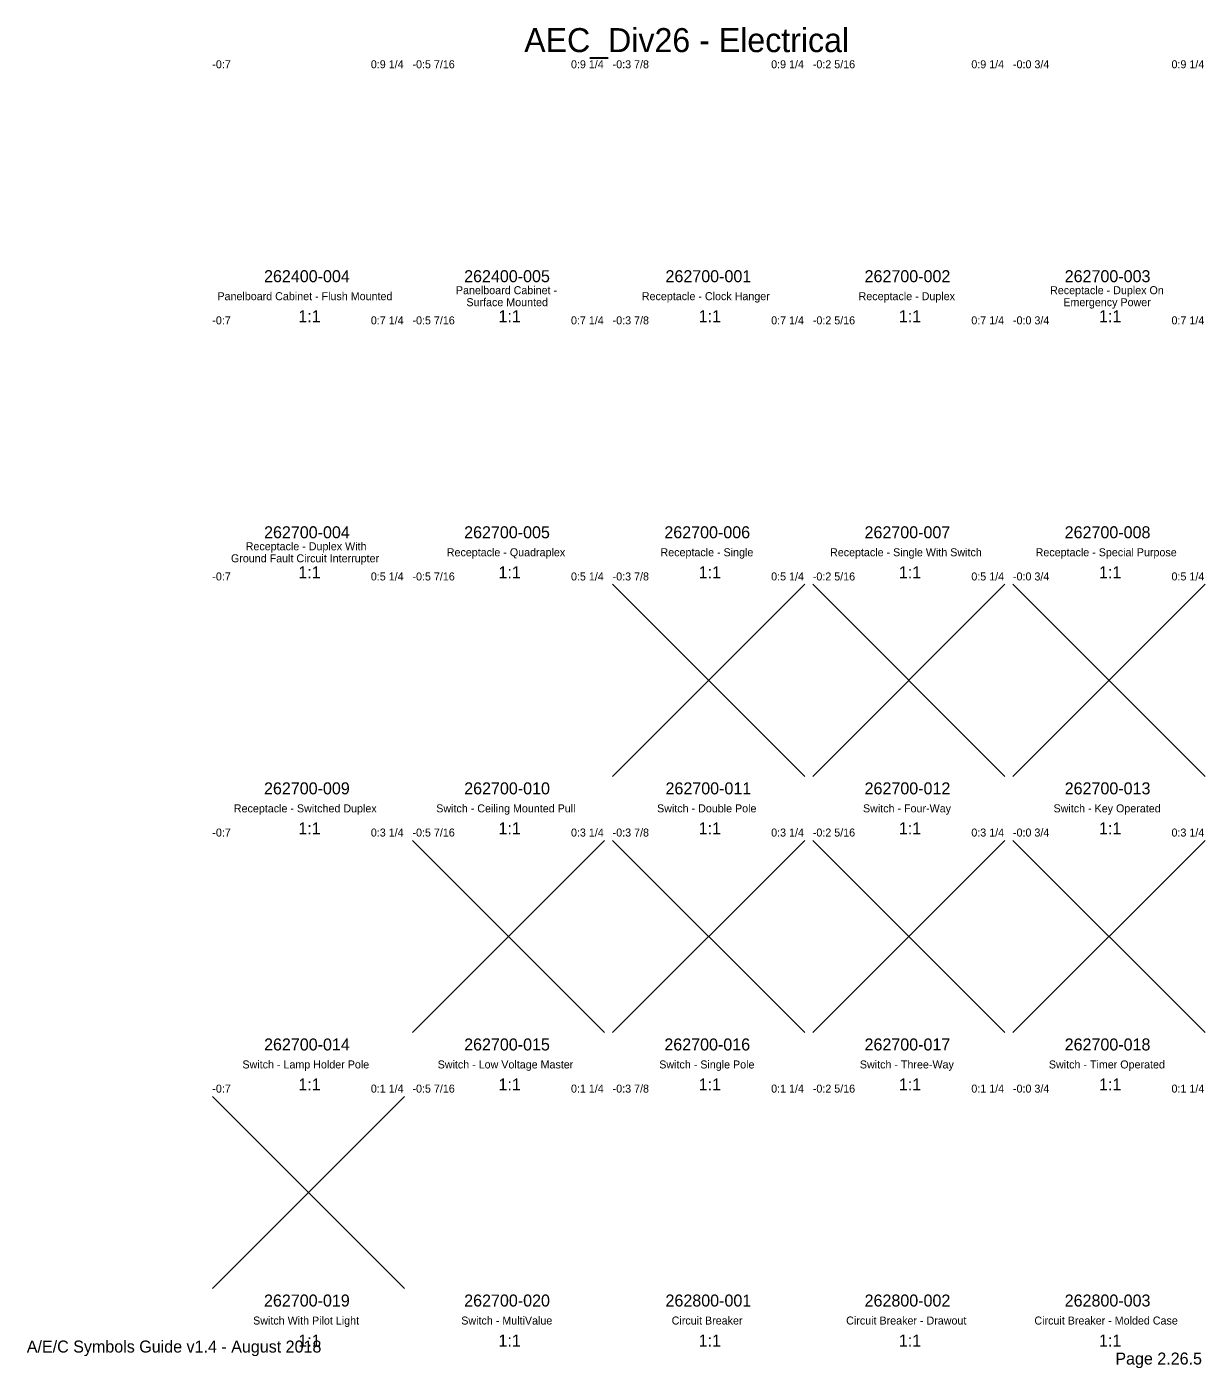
# Model space of a CAD drawing. Extents: x -0.8 to 0, y 0 to 31.6.
# Drawn here: x -0.766 to 0, y -0.01 to 0.863 of the extents above; entities that cross this region are included whole.
import ezdxf

# ---------------------------------------------------------------- set-up
doc = ezdxf.new("R2010")
doc.units = 0
for name, color, linetype in [('Cell1', 7, 'Continuous'), ('Cell10', 7, 'Continuous'), ('Cell11', 7, 'Continuous'), ('Cell12', 7, 'Continuous'), ('Cell13', 7, 'Continuous'), ('Cell14', 7, 'Continuous'), ('Cell15', 7, 'Continuous'), ('Cell16', 7, 'Continuous'), ('Cell17', 7, 'Continuous'), ('Cell18', 7, 'Continuous'), ('Cell19', 7, 'Continuous'), ('Cell2', 7, 'Continuous'), ('Cell20', 7, 'Continuous'), ('Cell21', 7, 'Continuous'), ('Cell22', 7, 'Continuous'), ('Cell23', 7, 'Continuous'), ('Cell24', 7, 'Continuous'), ('Cell25', 7, 'Continuous'), ('Cell3', 7, 'Continuous'), ('Cell4', 7, 'Continuous'), ('Cell5', 7, 'Continuous'), ('Cell6', 7, 'Continuous'), ('Cell7', 7, 'Continuous'), ('Cell8', 7, 'Continuous'), ('Cell9', 7, 'Continuous'), ('Default', 7, 'Continuous'), ('G-ANNO-REDL', 7, 'Continuous'), ('G-ANNO-TEXT', 7, 'Continuous'), ('OriginText', 7, 'Continuous')]:
    doc.layers.add(name, color=color, linetype=linetype)

msp = doc.modelspace()

# ---------------------------------------------------------------- linework, layer by layer
at = {"layer": 'G-ANNO-REDL'}
for p, q in [((-0.38542, 0.5), (-0.26042, 0.375)), ((-0.38542, 0.375), (-0.26042, 0.5)), ((-0.25521, 0.5), (-0.13021, 0.375)), ((-0.25521, 0.375), (-0.13021, 0.5)), ((-0.125, 0.5), (0, 0.375)), ((-0.125, 0.375), (0, 0.5)), ((-0.51563, 0.33333), (-0.39063, 0.20833)), ((-0.51563, 0.20833), (-0.39063, 0.33333)), ((-0.38542, 0.33333), (-0.26042, 0.20833)), ((-0.38542, 0.20833), (-0.26042, 0.33333)), ((-0.25521, 0.33333), (-0.13021, 0.20833)), ((-0.25521, 0.20833), (-0.13021, 0.33333)), ((-0.125, 0.33333), (0, 0.20833)), ((-0.125, 0.20833), (0, 0.33333)), ((-0.64583, 0.16667), (-0.52083, 0.04167)), ((-0.64583, 0.04167), (-0.52083, 0.16667))]:
    msp.add_line(p, q, dxfattribs=at)

# ---------------------------------------------------------------- texts
at = {"layer": 'Cell1'}
for s, height, p in [('262400-004', 0.007813, (-0.61219, 0.69662)), ('Panelboard Cabinet - Flush Mounted', 0.0052083, (-0.64252, 0.6849)), ('1:1', 0.007813, (-0.58991, 0.67057))]:
    msp.add_text(s, height=height, dxfattribs=at).set_placement(p)
at = {"layer": 'Cell10'}
for s, height, p in [('262700-008', 0.007813, (-0.09138, 0.52995)), ('Receptacle - Special Purpose', 0.0052083, (-0.11027, 0.51823)), ('1:1', 0.007813, (-0.06908, 0.50391))]:
    msp.add_text(s, height=height, dxfattribs=at).set_placement(p)
at = {"layer": 'Cell11'}
for s, height, p in [('262700-009', 0.007813, (-0.61221, 0.36328)), ('Receptacle - Switched Duplex', 0.0052083, (-0.63183, 0.35156)), ('1:1', 0.007813, (-0.58991, 0.33724))]:
    msp.add_text(s, height=height, dxfattribs=at).set_placement(p)
at = {"layer": 'Cell12'}
for s, height, p in [('262700-010', 0.007813, (-0.48199, 0.36328)), ('Switch - Ceiling Mounted Pull', 0.0052083, (-0.50018, 0.35156)), ('1:1', 0.007813, (-0.45971, 0.33724))]:
    msp.add_text(s, height=height, dxfattribs=at).set_placement(p)
at = {"layer": 'Cell13'}
for s, height, p in [('262700-011', 0.007813, (-0.35104, 0.36328)), ('Switch - Double Pole', 0.0052083, (-0.35653, 0.35156)), ('1:1', 0.007813, (-0.3295, 0.33724))]:
    msp.add_text(s, height=height, dxfattribs=at).set_placement(p)
at = {"layer": 'Cell14'}
for s, height, p in [('262700-012', 0.007813, (-0.22154, 0.36328)), ('Switch - Four-Way', 0.0052083, (-0.22259, 0.35156)), ('1:1', 0.007813, (-0.19929, 0.33724))]:
    msp.add_text(s, height=height, dxfattribs=at).set_placement(p)
at = {"layer": 'Cell15'}
for s, height, p in [('262700-013', 0.007813, (-0.09137, 0.36328)), ('Switch - Key Operated', 0.0052083, (-0.09863, 0.35156)), ('1:1', 0.007813, (-0.06908, 0.33724))]:
    msp.add_text(s, height=height, dxfattribs=at).set_placement(p)
at = {"layer": 'Cell16'}
for s, height, p in [('262700-014', 0.007813, (-0.61219, 0.19661)), ('Switch - Lamp Holder Pole', 0.0052083, (-0.62625, 0.1849)), ('1:1', 0.007813, (-0.58991, 0.17057))]:
    msp.add_text(s, height=height, dxfattribs=at).set_placement(p)
at = {"layer": 'Cell17'}
for s, height, p in [('262700-015', 0.007813, (-0.48203, 0.19661)), ('Switch - Low Voltage Master', 0.0052083, (-0.49927, 0.1849)), ('1:1', 0.007813, (-0.45971, 0.17057))]:
    msp.add_text(s, height=height, dxfattribs=at).set_placement(p)
at = {"layer": 'Cell18'}
for s, height, p in [('262700-016', 0.007813, (-0.35179, 0.19661)), ('Switch - Single Pole', 0.0052083, (-0.35512, 0.18489)), ('1:1', 0.007813, (-0.3295, 0.17057))]:
    msp.add_text(s, height=height, dxfattribs=at).set_placement(p)
at = {"layer": 'Cell19'}
for s, height, p in [('262700-017', 0.007813, (-0.22158, 0.19661)), ('Switch - Three-Way', 0.0052083, (-0.22461, 0.1849)), ('1:1', 0.007813, (-0.19929, 0.17057))]:
    msp.add_text(s, height=height, dxfattribs=at).set_placement(p)
at = {"layer": 'Cell2'}
for s, height, p in [('262400-005', 0.007813, (-0.48203, 0.69662)), ('Panelboard Cabinet - ', 0.0052083, (-0.48739, 0.6888)), ('Surface Mounted', 0.0052083, (-0.48056, 0.68099)), ('1:1', 0.007813, (-0.45971, 0.67057))]:
    msp.add_text(s, height=height, dxfattribs=at).set_placement(p)
at = {"layer": 'Cell20'}
for s, height, p in [('262700-018', 0.007813, (-0.09138, 0.19661)), ('Switch - Timer Operated', 0.0052083, (-0.10166, 0.1849)), ('1:1', 0.007813, (-0.06908, 0.17057))]:
    msp.add_text(s, height=height, dxfattribs=at).set_placement(p)
at = {"layer": 'Cell21'}
for s, height, p in [('262700-019', 0.007813, (-0.61221, 0.02995)), ('Switch With Pilot Light', 0.0052083, (-0.61929, 0.01823)), ('1:1', 0.007813, (-0.58991, 0.00391))]:
    msp.add_text(s, height=height, dxfattribs=at).set_placement(p)
at = {"layer": 'Cell22'}
for s, height, p in [('262700-020', 0.007813, (-0.48199, 0.02995)), ('Switch - MultiValue', 0.0052083, (-0.48391, 0.01823)), ('1:1', 0.007813, (-0.45971, 0.00391))]:
    msp.add_text(s, height=height, dxfattribs=at).set_placement(p)
at = {"layer": 'Cell23'}
for s, height, p in [('262800-001', 0.007813, (-0.35104, 0.02995)), ('Circuit Breaker', 0.0052083, (-0.34702, 0.01823)), ('1:1', 0.007813, (-0.3295, 0.0039))]:
    msp.add_text(s, height=height, dxfattribs=at).set_placement(p)
at = {"layer": 'Cell24'}
for s, height, p in [('262800-002', 0.007813, (-0.22154, 0.02995)), ('Circuit Breaker - Drawout', 0.0052083, (-0.23351, 0.01823)), ('1:1', 0.007813, (-0.19929, 0.00391))]:
    msp.add_text(s, height=height, dxfattribs=at).set_placement(p)
at = {"layer": 'Cell25'}
for s, height, p in [('262800-003', 0.007813, (-0.09137, 0.02995)), ('Circuit Breaker - Molded Case', 0.0052083, (-0.11107, 0.01823)), ('1:1', 0.007813, (-0.06908, 0.00391))]:
    msp.add_text(s, height=height, dxfattribs=at).set_placement(p)
at = {"layer": 'Cell3'}
for s, height, p in [('262700-001', 0.007813, (-0.35104, 0.69661)), ('Receptacle - Clock Hanger', 0.0052083, (-0.36644, 0.6849)), ('1:1', 0.007813, (-0.3295, 0.67057))]:
    msp.add_text(s, height=height, dxfattribs=at).set_placement(p)
at = {"layer": 'Cell4'}
for s, height, p in [('262700-002', 0.007813, (-0.22154, 0.69662)), ('Receptacle - Duplex', 0.0052083, (-0.22544, 0.6849)), ('1:1', 0.007813, (-0.19929, 0.67057))]:
    msp.add_text(s, height=height, dxfattribs=at).set_placement(p)
at = {"layer": 'Cell5'}
for s, height, p in [('262700-003', 0.007813, (-0.09137, 0.69662)), ('Receptacle - Duplex On ', 0.0052083, (-0.10087, 0.6888)), ('Emergency Power', 0.0052083, (-0.09227, 0.68099)), ('1:1', 0.007813, (-0.06908, 0.67057))]:
    msp.add_text(s, height=height, dxfattribs=at).set_placement(p)
at = {"layer": 'Cell6'}
for s, height, p in [('262700-004', 0.007813, (-0.61219, 0.52995)), ('Receptacle - Duplex With ', 0.0052083, (-0.62413, 0.52214)), ('Ground Fault Circuit Interrupter', 0.0052083, (-0.63372, 0.51432)), ('1:1', 0.007813, (-0.58991, 0.50391))]:
    msp.add_text(s, height=height, dxfattribs=at).set_placement(p)
at = {"layer": 'Cell7'}
for s, height, p in [('262700-005', 0.007813, (-0.48203, 0.52995)), ('Receptacle - Quadraplex', 0.0052083, (-0.49333, 0.51823)), ('1:1', 0.007813, (-0.45971, 0.50391))]:
    msp.add_text(s, height=height, dxfattribs=at).set_placement(p)
at = {"layer": 'Cell8'}
for s, height, p in [('262700-006', 0.007813, (-0.35179, 0.52995)), ('Receptacle - Single', 0.0052083, (-0.35431, 0.51823)), ('1:1', 0.007813, (-0.3295, 0.50391))]:
    msp.add_text(s, height=height, dxfattribs=at).set_placement(p)
at = {"layer": 'Cell9'}
for s, height, p in [('262700-007', 0.007813, (-0.22158, 0.52995)), ('Receptacle - Single With Switch', 0.0052083, (-0.24402, 0.51823)), ('1:1', 0.007813, (-0.19929, 0.50391))]:
    msp.add_text(s, height=height, dxfattribs=at).set_placement(p)
at = {"layer": 'Default'}
msp.add_text('AEC_Div26 - Electrical', height=0.015625, dxfattribs=at).set_placement((-0.44295, 0.84635))
at = {"layer": 'G-ANNO-TEXT'}
for s, p in [('A/E/C Symbols Guide v1.4 - August 2018', (-0.76652, 0)), ('Page 2.26.5', (-0.05842, -0.00781))]:
    msp.add_text(s, height=0.0078125, dxfattribs=at).set_placement(p)
at = {"layer": 'OriginText'}
for s, p in [('-0:7', (-0.64583, 0.83583)), ('0:9 1/4', (-0.54272, 0.83583)), ('-0:5 7/16', (-0.51563, 0.83583)), ('0:9 1/4', (-0.41252, 0.83583)), ('-0:3 7/8', (-0.38542, 0.83583)), ('0:9 1/4', (-0.28231, 0.83583)), ('-0:2 5/16', (-0.25521, 0.83583)), ('0:9 1/4', (-0.1521, 0.83583)), ('-0:0 3/4', (-0.125, 0.83583)), ('0:9 1/4', (-0.02189, 0.83583)), ('-0:7', (-0.64583, 0.66917)), ('0:7 1/4', (-0.54272, 0.66917)), ('-0:5 7/16', (-0.51563, 0.66917)), ('0:7 1/4', (-0.41252, 0.66917)), ('-0:3 7/8', (-0.38542, 0.66917)), ('0:7 1/4', (-0.28231, 0.66917)), ('-0:2 5/16', (-0.25521, 0.66917)), ('0:7 1/4', (-0.1521, 0.66917)), ('-0:0 3/4', (-0.125, 0.66917)), ('0:7 1/4', (-0.02189, 0.66917)), ('-0:7', (-0.64583, 0.5025)), ('0:5 1/4', (-0.54272, 0.5025)), ('-0:5 7/16', (-0.51563, 0.5025)), ('0:5 1/4', (-0.41252, 0.5025)), ('-0:3 7/8', (-0.38542, 0.5025)), ('0:5 1/4', (-0.28231, 0.5025)), ('-0:2 5/16', (-0.25521, 0.5025)), ('0:5 1/4', (-0.1521, 0.5025)), ('-0:0 3/4', (-0.125, 0.5025)), ('0:5 1/4', (-0.02189, 0.5025)), ('-0:7', (-0.64583, 0.33583)), ('0:3 1/4', (-0.54272, 0.33583)), ('-0:5 7/16', (-0.51563, 0.33583)), ('0:3 1/4', (-0.41252, 0.33583)), ('-0:3 7/8', (-0.38542, 0.33583)), ('0:3 1/4', (-0.28231, 0.33583)), ('-0:2 5/16', (-0.25521, 0.33583)), ('0:3 1/4', (-0.1521, 0.33583)), ('-0:0 3/4', (-0.125, 0.33583)), ('0:3 1/4', (-0.02189, 0.33583)), ('0:1 1/4', (-0.54272, 0.16917)), ('-0:5 7/16', (-0.51563, 0.16917)), ('0:1 1/4', (-0.41252, 0.16917)), ('-0:3 7/8', (-0.38542, 0.16917)), ('0:1 1/4', (-0.28231, 0.16917)), ('-0:2 5/16', (-0.25521, 0.16917)), ('0:1 1/4', (-0.1521, 0.16917)), ('-0:0 3/4', (-0.125, 0.16917)), ('0:1 1/4', (-0.02189, 0.16917)), ('-0:7', (-0.64583, 0.16917))]:
    msp.add_text(s, height=0.005208, dxfattribs=at).set_placement(p)

doc.saveas('drawing.dxf')
